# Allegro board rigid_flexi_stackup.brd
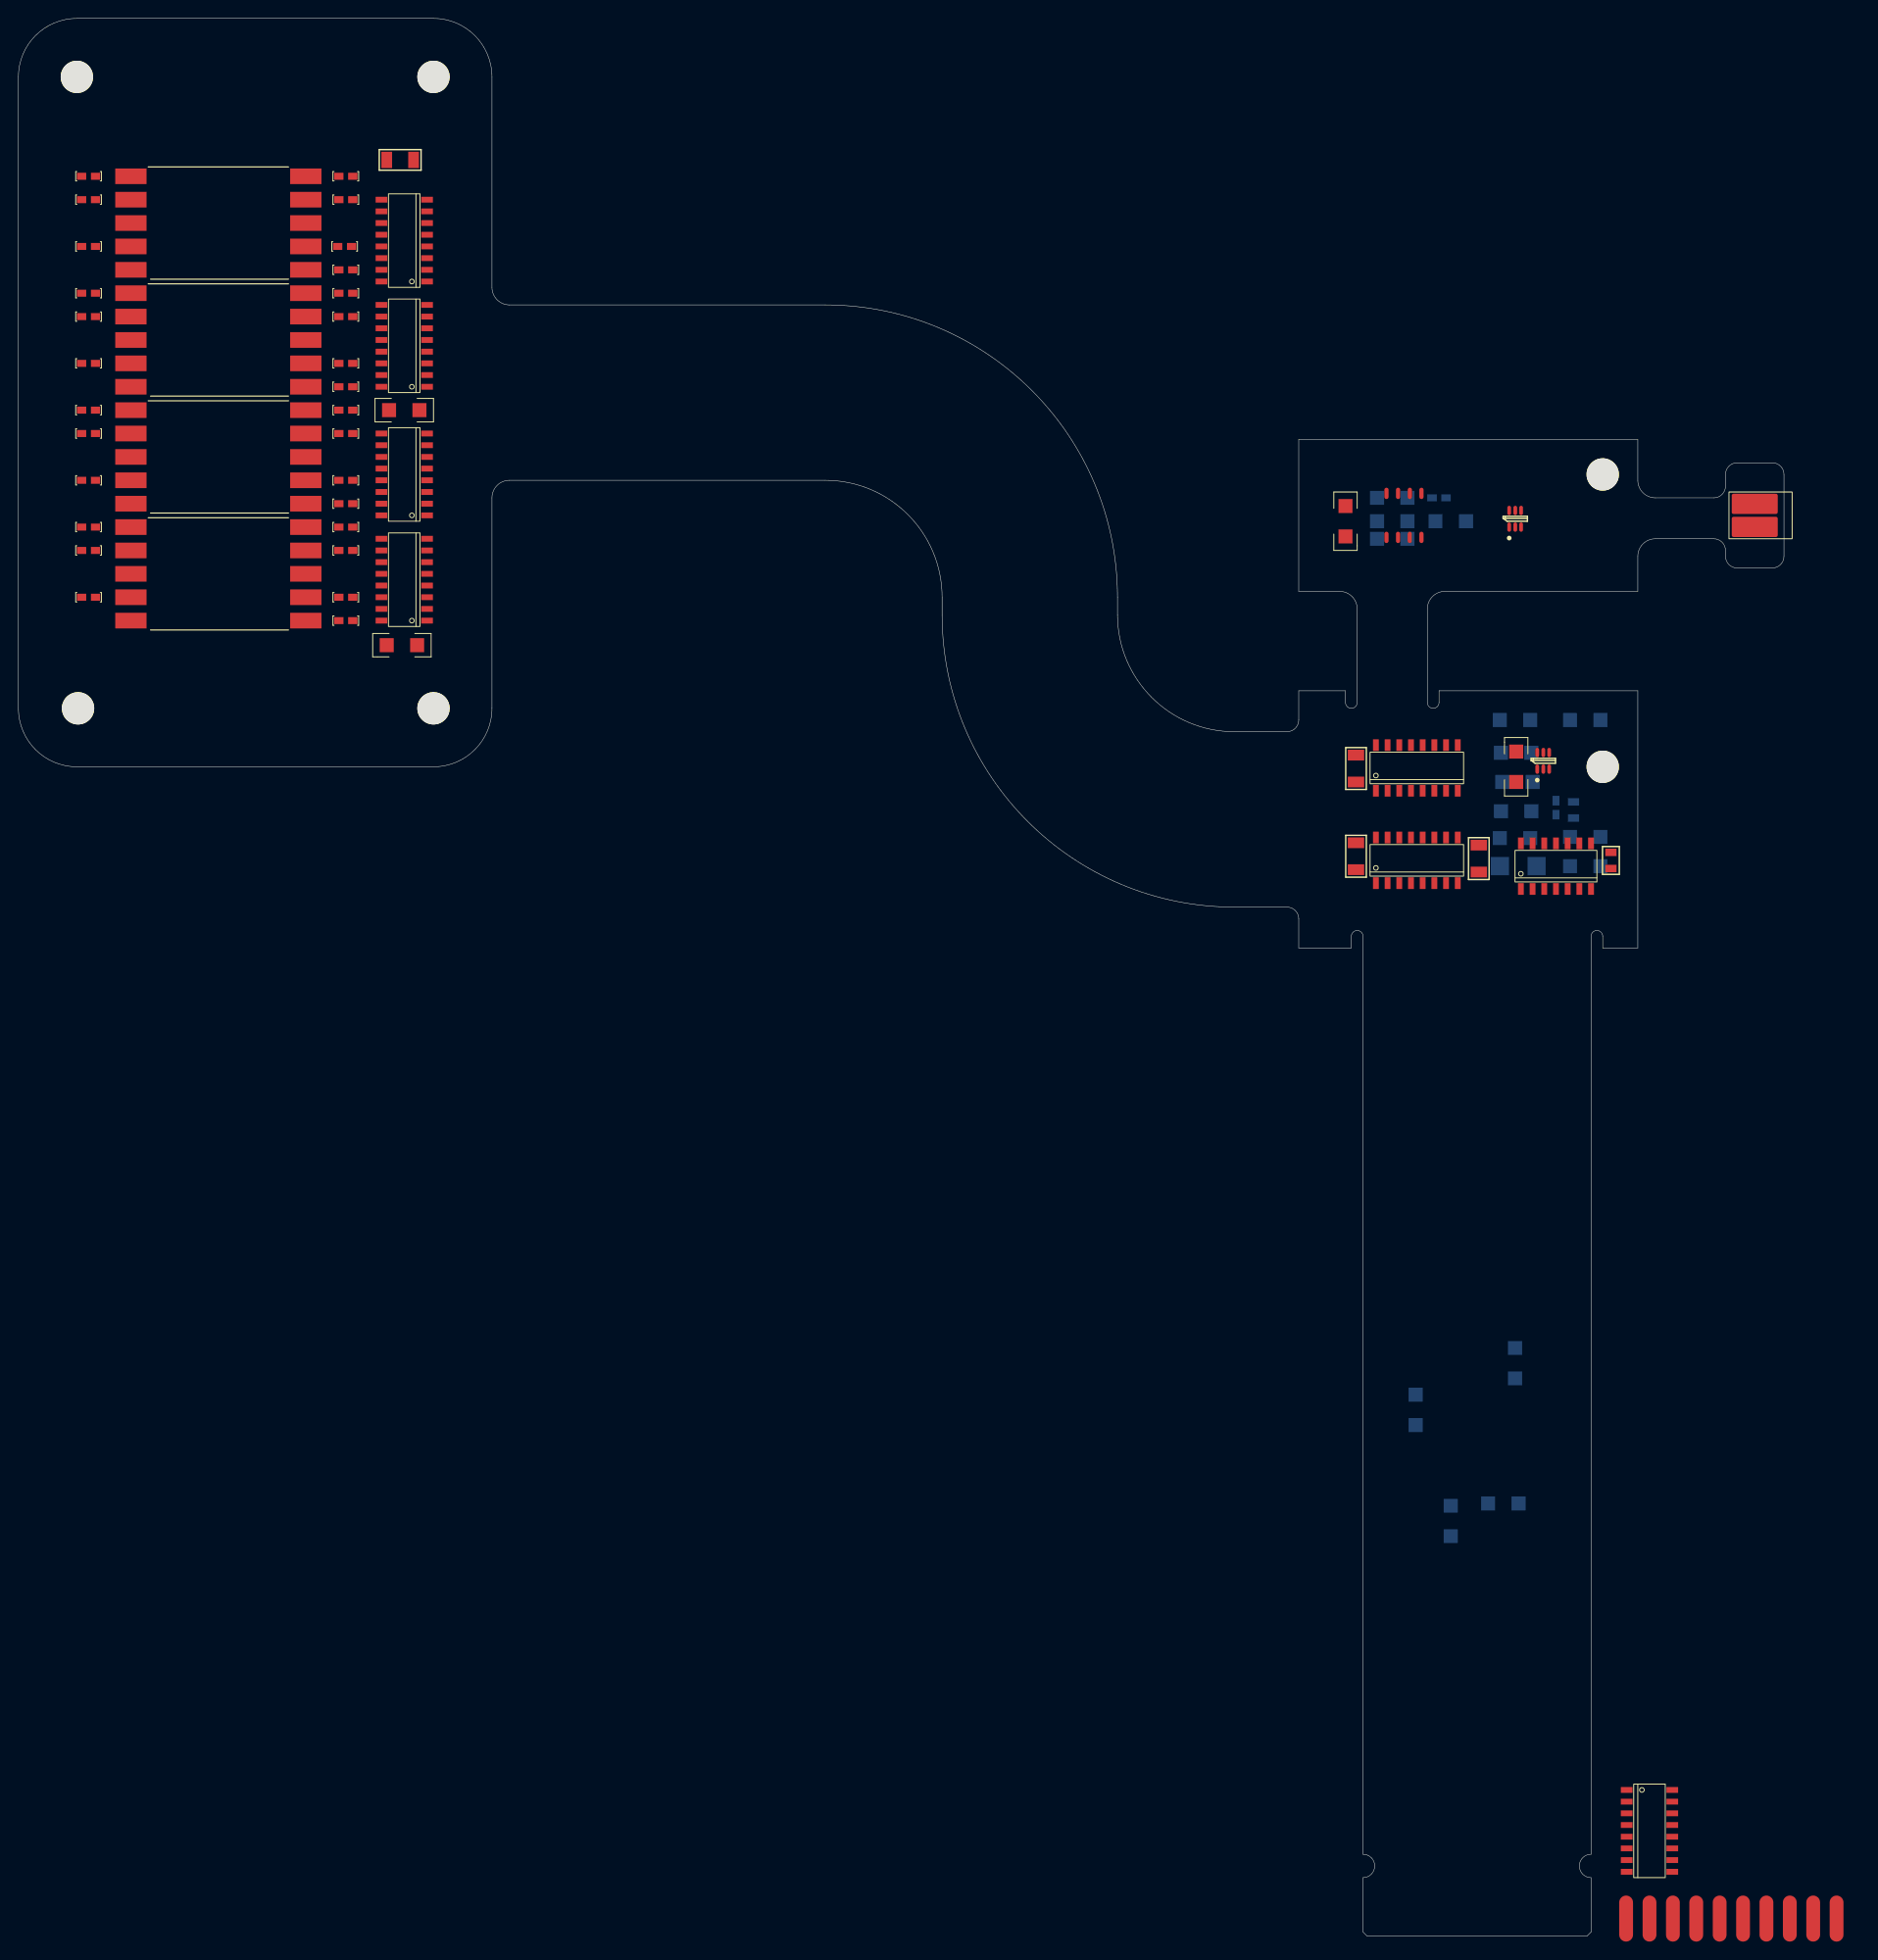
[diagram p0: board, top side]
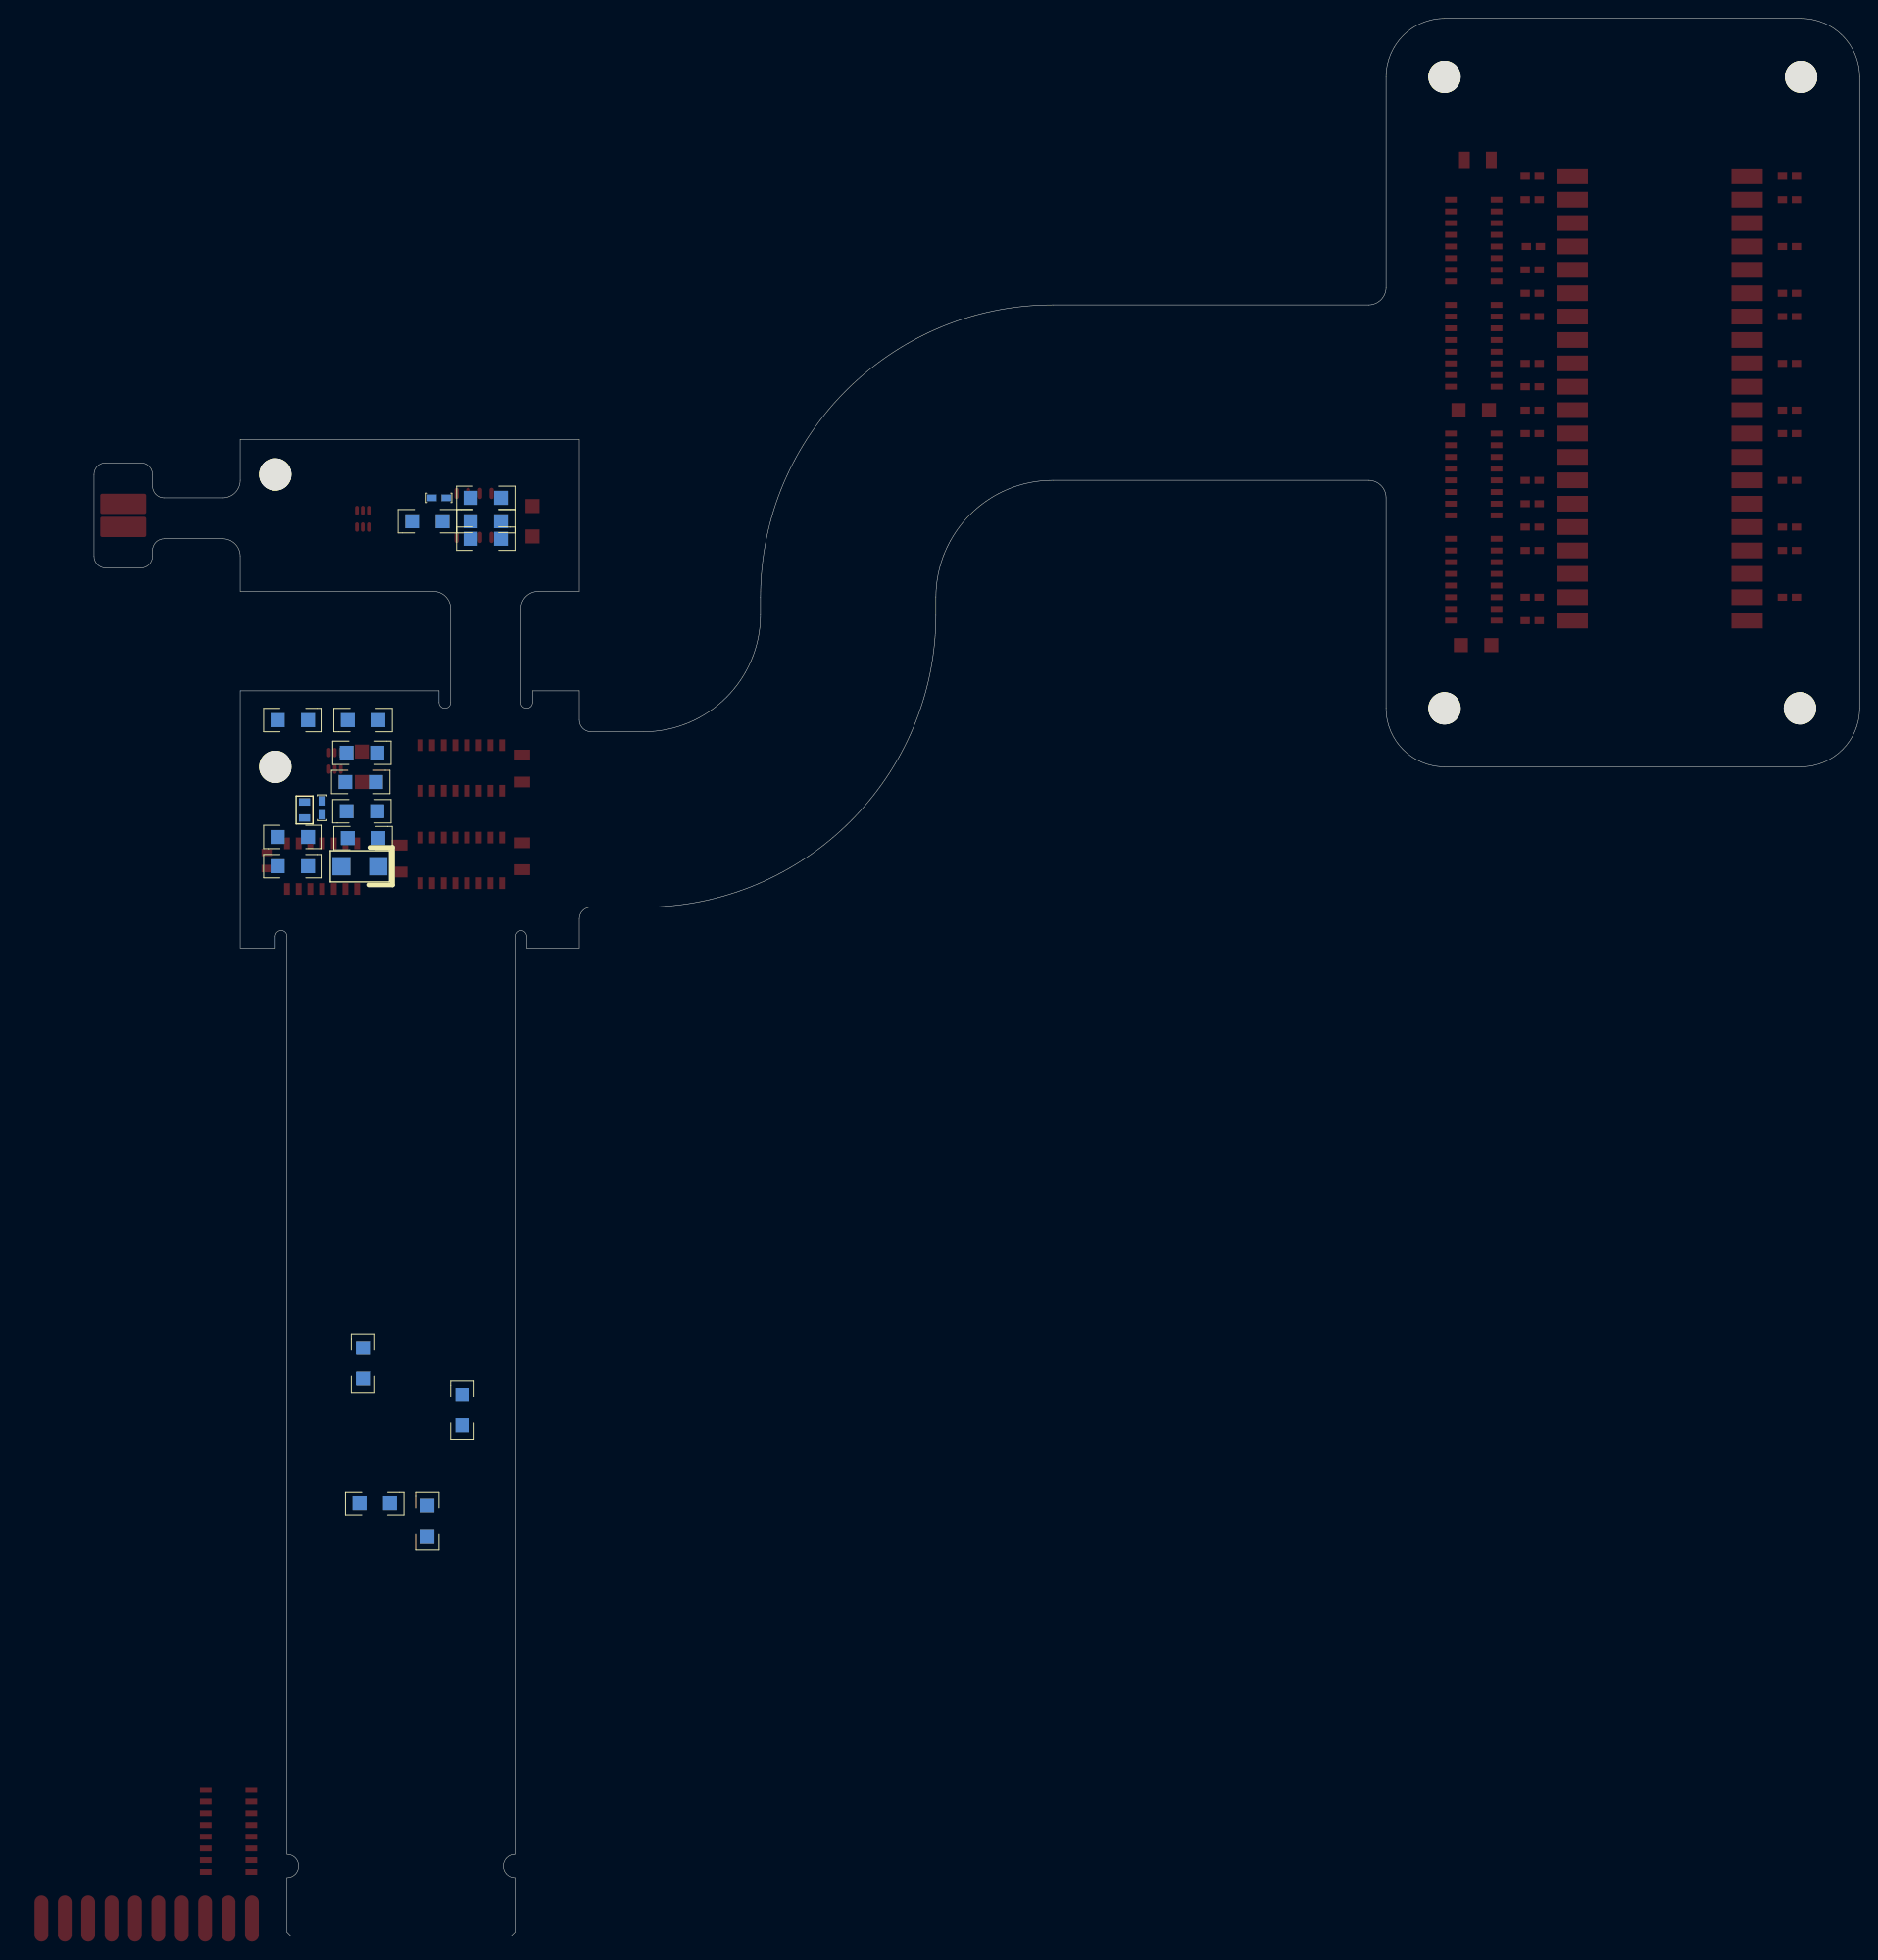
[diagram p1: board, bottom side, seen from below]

Outline 191.77 x 208.28 mm; copper layers: TOP, INT_1, FLEX_1, FLEX_2, INT_4, BOTTOM. Coordinates in mm from the lower left corner of the outline.
Outline path: 0,201.93 0,133.35 arc(1.86,128.86) 6.35,127 45.08,127 arc(49.58,128.86) 51.43,133.35 51.43,156.21 arc(51.99,157.56) 53.34,158.12 87.63,158.12 arc(96.61,154.4) 100.33,145.41 100.33,143.51 arc(109.63,121.06) 132.08,111.76 137.8,111.76 arc(138.69,111.39) 139.06,110.49 139.06,107.31 144.78,107.31 144.78,108.59 arc(145.41,109.22) 146.05,108.59 146.05,8.89 arc(147.32,7.62) 146.05,6.35 146.05,0.45 146.5,0 170.37,0 170.81,0.45 170.81,6.35 arc(169.55,7.62) 170.81,8.89 170.81,108.59 arc(171.45,109.22) 172.08,108.59 172.08,107.31 175.89,107.31 175.89,135.25 154.31,135.25 154.31,133.99 arc(153.67,133.35) 153.03,133.99 153.03,144.14 arc(153.59,145.49) 154.94,146.05 175.89,146.05 175.89,149.86 arc(176.45,151.21) 177.8,151.76 184.15,151.76 arc(185.05,151.39) 185.42,150.5 185.42,149.86 arc(185.79,148.96) 186.69,148.59 190.5,148.59 arc(191.4,148.96) 191.77,149.86 191.77,158.75 arc(191.4,159.65) 190.5,160.02 186.69,160.02 arc(185.79,159.65) 185.42,158.75 185.42,157.48 arc(185.05,156.58) 184.15,156.21 177.8,156.21 arc(176.45,156.77) 175.89,158.12 175.89,162.56 139.06,162.56 139.06,146.05 143.51,146.05 arc(144.86,145.49) 145.41,144.14 145.41,133.99 arc(144.78,133.35) 144.14,133.99 144.14,135.25 139.06,135.25 139.06,132.08 arc(138.69,131.18) 137.8,130.81 132.08,130.81 arc(123.1,134.53) 119.38,143.51 119.38,145.41 arc(110.08,167.87) 87.63,177.17 53.34,177.17 arc(51.99,177.72) 51.43,179.07 51.43,201.93 arc(49.58,206.42) 45.08,208.28 6.35,208.28 arc(1.86,206.42) 0,201.93

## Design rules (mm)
constraint set DEFAULT: min track width 0.254
nets with their own width: min track width 0.381; nets GND

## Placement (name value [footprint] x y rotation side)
B1  -  [BATT1]  188.59 154.31 90 top
C1  -  [A_MC-1206_A]  145.29 115.82 90 top
C2  -  [A_MC-1206_A]  145.29 125.35 90 top
C3  -  [A_MC-1206_A]  158.62 115.57 90 top
C4  -  [A_MC-1206_A]  42.93 192.91 180 top
C5  .001UF  [1206RF_WV_12D]  149.22 151.76 180 bottom
C6  .001UF  [1206RF_WV_12D]  149.22 153.67 180 bottom
C7  .001UF  [1206RF_WV_12D]  149.22 156.21 0 bottom
C8  .001UF  [1206RF_WV_12D]  155.57 45.09 90 bottom
C9  .001UF  [1206RF_WV_12D]  162.69 122.17 0 bottom
C10  .001UF  [1206RF_WV_12D]  41.91 165.74 0 top
C11  .001UF  [1206RF_WV_12D]  41.66 140.21 180 top
C12  .1UF  [0603RF_WV_12D]  154.31 156.21 180 bottom
C13  .1UF  [0603RF_WV_12D]  167 122.56 270 bottom
C14  10UF  [1206RF_WV_12D]  162.56 62.23 90 bottom
C15  10UF  [1206RF_WV_12D]  162.69 128.52 180 bottom
D1  1N4148  [A_CR-0805]  168.91 123.19 270 bottom
D2  1N4148  [A_CR-0805]  172.97 115.95 90 top
D3  20V  [A_DIODE-157]  160.91 116.2 0 bottom
DSP1  -  [LED-DISPLAY]  21.72 186.06 270 top
DSP2  -  [LED-DISPLAY]  21.72 173.36 270 top
DSP3  -  [LED-DISPLAY]  21.72 160.66 270 top
DSP4  -  [LED-DISPLAY]  21.72 147.95 270 top
J1  -  [CONN10]  174.62 1.91 0 top
NOREF  -  [unnamed]  6.48 133.35 0 top
NOREF#2  -  [unnamed]  6.35 201.93 0 top
NOREF#3  -  [unnamed]  172.08 127 0 top
NOREF#4  -  [unnamed]  45.08 133.35 0 top
NOREF#5  -  [unnamed]  45.08 201.93 0 top
NOREF#6  -  [unnamed]  172.08 158.75 0 top
R1  390  [0603RF_WV_12D]  7.62 191.13 0 top
R2  390  [0603RF_WV_12D]  35.56 191.13 0 top
R3  390  [0603RF_WV_12D]  7.62 188.59 0 top
R4  390  [0603RF_WV_12D]  35.56 188.59 0 top
R5  390  [0603RF_WV_12D]  7.62 183.51 0 top
R6  390  [0603RF_WV_12D]  35.43 183.51 0 top
R7  390  [0603RF_WV_12D]  35.56 180.97 0 top
R8  390  [0603RF_WV_12D]  7.62 178.44 0 top
R9  390  [0603RF_WV_12D]  35.56 178.44 0 top
R10  390  [0603RF_WV_12D]  7.62 175.89 0 top
R11  390  [0603RF_WV_12D]  35.56 175.89 0 top
R12  390  [0603RF_WV_12D]  7.62 170.81 0 top
R13  390  [0603RF_WV_12D]  35.56 170.81 0 top
R14  390  [0603RF_WV_12D]  35.56 168.28 0 top
R15  390  [0603RF_WV_12D]  7.62 165.74 0 top
R16  390  [0603RF_WV_12D]  35.56 165.74 0 top
R17  390  [0603RF_WV_12D]  7.62 163.19 0 top
R18  390  [0603RF_WV_12D]  35.56 163.19 0 top
R19  390  [0603RF_WV_12D]  7.62 158.12 0 top
R20  390  [0603RF_WV_12D]  35.56 158.12 0 top
R21  390  [0603RF_WV_12D]  35.56 155.57 0 top
R22  390  [0603RF_WV_12D]  7.62 153.03 0 top
R23  390  [0603RF_WV_12D]  35.56 153.03 0 top
R24  390  [0603RF_WV_12D]  7.62 150.5 0 top
R25  390  [0603RF_WV_12D]  35.56 150.5 0 top
R26  390  [0603RF_WV_12D]  7.62 145.41 0 top
R27  390  [0603RF_WV_12D]  35.56 145.41 0 top
R28  390  [0603RF_WV_12D]  35.56 142.88 0 top
R29  15K  [1206RF_WV_12D]  170.18 116.2 180 bottom
R30  15K  [1206RF_WV_12D]  162.56 119.25 180 bottom
R31  10K  [1206RF_WV_12D]  144.14 153.67 270 top
R32  10K  [1206RF_WV_12D]  155.57 153.67 0 bottom
R33  10K  [1206RF_WV_12D]  162.69 127 90 top
R34  10K  [1206RF_WV_12D]  170.18 119.38 0 bottom
R35  10K  [1206RF_WV_12D]  162.56 132.08 0 bottom
R36  100K  [1206RF_WV_12D]  161.29 46.99 180 bottom
R37  100K  [1206RF_WV_12D]  162.81 125.35 180 bottom
R38  12K  [1206RF_WV_12D]  151.76 57.15 90 bottom
R39  3.3K  [1206RF_WV_12D]  170.18 132.08 180 bottom
RV1  10K  [A_SOT363]  164.97 126.75 0 top
RV2  10K  [A_SOT363]  161.93 153.03 0 top
U1  ***  [SOIC16]  41.91 184.15 180 top
U2  ***  [SOIC16]  41.91 172.72 180 top
U3  ***  [SOIC16]  41.91 158.75 180 top
U4  ***  [SOIC16]  41.91 147.32 180 top
U5  ***  [SOIC16]  151.89 126.87 90 top
U6  ***  [SOIC16]  151.89 116.84 90 top
U7  ***  [SOIC16]  177.16 11.43 0 top
U8  -  [SOIC8]  150.5 154.31 90 top
U9  ***  [SOIC14]  167.64 116.2 90 top

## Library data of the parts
B1 = BATT1
C1-C4 = CAP15UF
C5-C11 = CAP: tolerance: 10%
C12-C15 = CAP
D1 D2 = 1N4148
D3 = 20V-RCT
DSP1-DSP4 = DISPLAY-LED
J1 = CONN10
R1-R28 = RES_RES0201_DISCRETE_0.3 MM_10K
R29-R39 = RES: tolerance: 5%
RV1 RV2 = VRES
U1-U4 = CD4511
U5 U6 = CD4518
U7 = CD4098
U8 = NE555
U9 = SN7400

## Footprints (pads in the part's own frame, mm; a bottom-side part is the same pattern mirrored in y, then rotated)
0603RF_WV_12D
  rect 1.016x0.762 smd: 1(-0.762,0) 2(0.762,0)
1206RF_WV_12D
  rect 1.524x1.524 smd: 1(-1.651,0) 2(1.651,0)
A_CR-0805
  rect 0.813x1.219 smd: 1(0,0) 2(1.753,0)
A_DIODE-157
  rect 1.981x1.981 smd: 1(0,0) 2(3.988,0)
A_MC-1206_A
  rect 1.168x1.778 smd: 1(0,0) 2(2.921,0)
A_SOT363
  custom 0.102x0.102 smd: 1(0,0) 2(0.66,0) 3(1.295,0) 4(1.295,1.803) 5(0.66,1.803) 6(0,1.803)
BATT1
  rrect 2.2x5 smd: 1(-1.25,0) 2(1.25,0)
CONN10
  oval 1.5x5 smd: 1(0,0) 2(2.54,0) 3(5.08,0) 4(7.62,0) 5(10.16,0) 6(12.7,0) 7(15.24,0) 8(17.78,0) 9(20.32,0) 10(22.86,0)
LED-DISPLAY
  rect 1.7x3.4 smd: 1(-5.08,-9.5) 2(-2.54,-9.5) 3(0,-9.5) 4(2.54,-9.5) 5(5.08,-9.5) 6(5.08,9.5) 7(2.54,9.5) 8(0,9.5) 9(-2.54,9.5) 10(-5.08,9.5)
SOIC8
  oval 1.23x0.46 smd: 1(-2.39,1.9) 2(-2.39,0.64) 3(-2.39,-0.63) 4(-2.39,-1.9) 5(2.39,-1.9) 6(2.39,-0.64) 7(2.39,0.64) 8(2.39,1.9)
SOIC14
  rect 1.27x0.635 smd: 1(-2.477,4.445) 2(-2.477,3.175) 3(-2.477,1.905) 4(-2.477,0.635) 5(-2.477,-0.635) 6(-2.477,-1.905) 7(-2.477,-3.175) 8(2.477,-3.175) 9(2.477,-1.905) 10(2.477,-0.635) 11(2.477,0.635) 12(2.477,1.905) 13(2.477,3.175) 14(2.477,4.445)
SOIC16
  rect 1.27x0.635 smd: 1(-2.477,4.445) 2(-2.477,3.175) 3(-2.477,1.905) 4(-2.477,0.635) 5(-2.477,-0.635) 6(-2.477,-1.905) 7(-2.477,-3.175) 8(-2.477,-4.445) 9(2.477,-4.445) 10(2.477,-3.175) 11(2.477,-1.905) 12(2.477,-0.635) 13(2.477,0.635) 14(2.477,1.905) 15(2.477,3.175) 16(2.477,4.445)
unnamed
  round 3.505 hole 3.505 unplated: (0,0)

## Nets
GND: B1.2 C1.1 C2.1 C3.1 C4.1 C5.2 C6.2 C7.1 C9.2 C10.2 C11.1 C12.1 C15.2 D3.2 DSP1.3 DSP1.8 DSP2.3 DSP2.8 DSP3.3 DSP3.8 DSP4.3 DSP4.8 J1.8 J1.9 J1.10 U1.8 U2.8 U3.8 U4.8 U5.1 U5.8 U6.1 U6.8 U7.3 U7.5 U7.8 U7.11 U7.13 U8.1 U9.7
VCC: B1.1 C1.2 C2.2 C3.2 C4.2 C5.1 C6.1 C10.1 C11.2 J1.1 J1.2 J1.3 R32.1 R33.1 R34.1 R35.2 R36.1 R37.1 R39.1 U1.3 U1.16 U2.3 U2.16 U3.3 U3.16 U4.3 U4.16 U5.16 U6.16 U7.16 U8.4 U9.14
A_1: U1.7 U5.11
A_2: U2.7 U5.3
A_3: U3.7 U6.11
A_4: U4.7 U6.3
B_1: U1.1 U5.12
B_2: U2.1 U5.4
B_3: U3.1 U6.12
B_4: U4.1 U6.4
C_1: U1.2 U5.13
C_2: U2.2 U5.5
C_3: U3.2 U6.13
C_4: U4.2 U6.5
D_1: U1.6 U5.2 U5.14
D_2: U2.6 U5.6
D_3: U3.6 U6.2 U6.14
D_4: U4.6 U6.6
F1_1: R1.1 U1.9
F1_2: R8.1 U2.9
F1_3: R15.1 U3.9
F1_4: R22.1 U4.9
F2_1: R3.1 U1.10
F2_2: R10.1 U2.10
F2_3: R17.1 U3.10
F2_4: R24.1 U4.10
F3_1: R5.1 U1.11
F3_2: R12.1 U2.11
F3_3: R19.1 U3.11
F3_4: R26.1 U4.11
F4_1: R7.2 U1.12
F4_2: R14.2 U2.12
F4_3: R21.2 U3.12
F4_4: R28.2 U4.12
F5_1: R6.2 U1.13
F5_2: R13.2 U2.13
F5_3: R20.2 U3.13
F5_4: R27.2 U4.13
F6_1: R4.2 U1.15
F6_2: R11.2 U2.15
F6_3: R18.2 U3.15
F6_4: R25.2 U4.15
F7_1: R2.2 U1.14
F7_2: R9.2 U2.14
F7_3: R16.2 U3.14
F7_4: R23.2 U4.14
INT: J1.6 RV1.5 U1.4 U2.4 U3.4 U4.4 U9.6
INT3: C15.1 D3.1 R35.1 R38.2
INT_N: J1.5 R32.2 RV2.2
LG1: D1.1 RV1.1
LG2: D2.2 RV1.3
LG3: D1.2 R30.1
LG4: D2.1 R29.1
N1_1: DSP1.1 R1.2
N1_2: DSP2.1 R8.2
N1_3: DSP3.1 R15.2
N1_4: DSP4.1 R22.2
N2_1: DSP1.2 R3.2
N2_2: DSP2.2 R10.2
N2_3: DSP3.2 R17.2
N2_4: DSP4.2 R24.2
N3_1: DSP1.4 R5.2
N3_2: DSP2.4 R12.2
N3_3: DSP3.4 R19.2
N3_4: DSP4.4 R26.2
N4_1: DSP1.6 R7.1
N4_2: DSP2.6 R14.1
N4_3: DSP3.6 R21.1
N4_4: DSP4.6 R28.1
N5_1: DSP1.7 R6.1
N5_2: DSP2.7 R13.1
N5_3: DSP3.7 R20.1
N5_4: DSP4.7 R27.1
N6_1: DSP1.9 R4.1
N6_2: DSP2.9 R11.1
N6_3: DSP3.9 R18.1
N6_4: DSP4.9 R25.1
N7_1: DSP1.10 R2.1
N7_2: DSP2.10 R9.1
N7_3: DSP3.10 R16.1
N7_4: DSP4.10 R23.1
NET000: U1.5 U2.5 U3.5 U4.5 U7.7 U7.12
NET001: U5.7 U5.15 U6.7 U6.15 U7.10
NET002: U7.4 U8.3
NET003: C7.2 R31.2 U8.2 U8.6
NET004: U5.9 U6.9 U9.1 U9.8
NET005: C9.1 R29.2 R30.2 U9.4 U9.5
SIG-IN: J1.7 R38.1
SIG_IN_N: J1.4 R33.2 RV1.2
TM1: R39.2 RV2.5
TM2: R31.1 RV2.1 RV2.3 U8.7
TM3: C12.2 U8.5
TM4: C8.2 R36.2 U7.1
TM5: C8.1 U7.2
TM6: C14.2 R37.2 U7.14
TM7: C14.1 U7.15
VC1: C13.2 U9.3
VC2: C13.1 R34.2 U9.9 U9.10

Pads without a net: DSP1 5; DSP2 5; DSP3 5; DSP4 5; RV1 4 6; RV2 4 6; U5 10; U6 10; U7 6 9; U8 8; U9 2 11 12 13
